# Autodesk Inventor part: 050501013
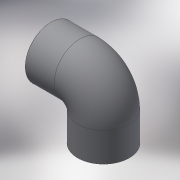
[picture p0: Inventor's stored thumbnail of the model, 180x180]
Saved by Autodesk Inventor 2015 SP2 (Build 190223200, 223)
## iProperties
Created: 2017-10
Part Number: 050501013
Material: Generic
Description: PLASSON THREADED 90° ELBOW PVC 1.1/4"
Document SubType Name: Modeling
Designer: KIM
Density: 1 g/cm^3
Appearance: Default
Author: KIM
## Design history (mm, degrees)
derived "050501.ipt"
feature "Solid1::050501.ipt"
tag "TaggingFeature1"
body "Solid1"
other parameters: "d7" = 0.38952, "d9" = 48, "d10" = 51, "d13" = 90 deg, "d19" = 90 deg, "d20" = 38.952, "d21" = 22, "d22" = 0, "d24" = 90 deg, "d26" = 35.0568, "d27" = 90 deg, "d28" = 22, "G_" = 38.952, "E_" = 48, "H_" = 75, "lt_" = 22
